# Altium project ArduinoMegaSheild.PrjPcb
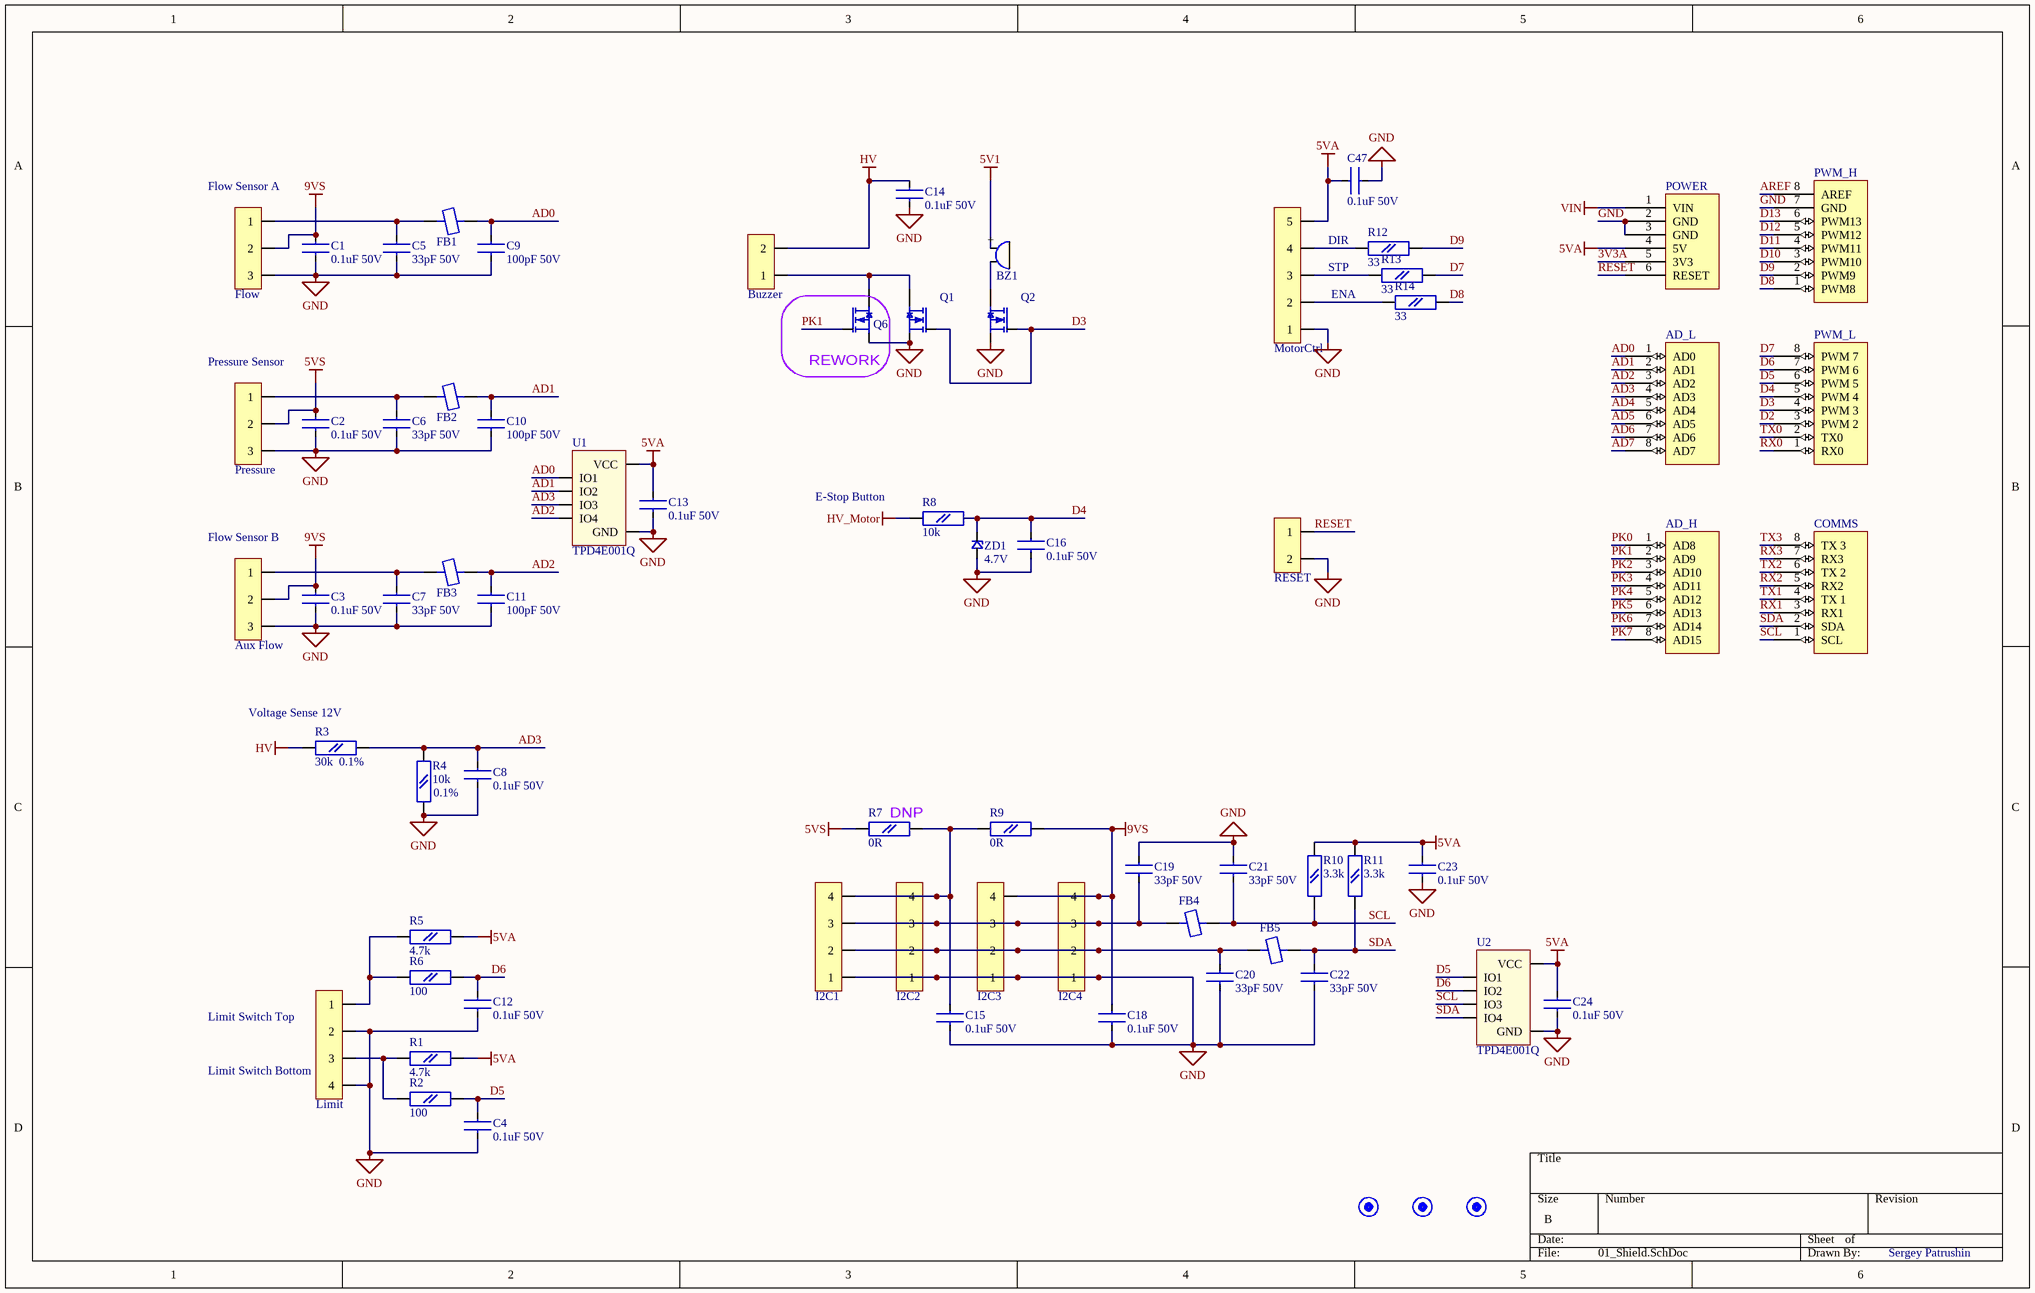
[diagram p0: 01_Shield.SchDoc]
3 sheets, 127 parts. Net scope: global (net labels, ports and power ports of the same name join across sheets).
Board file: MEGA_Shield_OVVP.pcbdoc
Sheets:
  01_Shield.SchDoc
  02_Power.SchDoc
  03_RPi.SchDoc

## Sheet 01_Shield.SchDoc
size B

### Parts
AD_H  AD_H  [Header 8x1 8.5mm]  (value not drawn)
AD_L  AD_L  [Header 8x1 8.5mm]  (value not drawn)
Aux_Flow  3pin JST  [3pin JST XH 2.5mm]  (value not drawn)
Buzzer  2pin JST  [2pin JST XH 2.5mm]  (value not drawn)
BZ1  BUZZER, 12mm X 9.5mm  [Buzzer]  (value not drawn)
C1  0.1uF 50V  [C np SMD 0805]
C2  0.1uF 50V  [C np SMD 0805]
C3  0.1uF 50V  [C np SMD 0805]
C4  0.1uF 50V  [C np SMD 0805]
C5  33pF 50V  [C np SMD 0805]
C6  33pF 50V  [C np SMD 0805]
C7  33pF 50V  [C np SMD 0805]
C8  0.1uF 50V  [C np SMD 0805]
C9  100pF 50V  [C np SMD 0805]
C10  100pF 50V  [C np SMD 0805]
C11  100pF 50V  [C np SMD 0805]
C12  0.1uF 50V  [C np SMD 0805]
C13  0.1uF 50V  [C np SMD 0805]
C14  0.1uF 50V  [C np SMD 0805]
C15  0.1uF 50V  [C np SMD 0805]
C16  0.1uF 50V  [C np SMD 0805]
C18  0.1uF 50V  [C np SMD 0805]
C19  33pF 50V  [C np SMD 0805]
C20  33pF 50V  [C np SMD 0805]
C21  33pF 50V  [C np SMD 0805]
C22  33pF 50V  [C np SMD 0805]
C23  0.1uF 50V  [C np SMD 0805]
C24  0.1uF 50V  [C np SMD 0805]
C47  0.1uF 50V  [C np SMD 0805]
COMMS  Communication  [Header 8x1 8.5mm]  (value not drawn)
F1  FIDUCIAL  [FIDUCIAL]  (value not drawn)
F2  FIDUCIAL  [FIDUCIAL]  (value not drawn)
F3  FIDUCIAL  [FIDUCIAL]  (value not drawn)
FB1  400mA  [R SMD 0805]  (value not drawn)
FB2  400mA  [R SMD 0805]  (value not drawn)
FB3  400mA  [R SMD 0805]  (value not drawn)
FB4  400mA  [R SMD 0805]  (value not drawn)
FB5  400mA  [R SMD 0805]  (value not drawn)
Flow  3pin JST  [3pin JST XH 2.5mm]  (value not drawn)
I2C1  4pin JST  [4pin JST XH 2.5mm]  (value not drawn)
I2C2  4pin JST  [4pin JST XH 2.5mm]  (value not drawn)
I2C3  4pin JST  [4pin JST XH 2.5mm]  (value not drawn)
I2C4  4pin JST  [4pin JST XH 2.5mm]  (value not drawn)
Limit  4pin JST  [4pin JST XH 2.5mm]  (value not drawn)
MotorCtrl  5pin JST  [5pin JST XH 2.5mm]  (value not drawn)
POWER  POWER  [Header 6x1 8.5mm]  (value not drawn)
Pressure  3pin JST  [3pin JST XH 2.5mm]  (value not drawn)
PWM_H  PWM_H  [Header 8x1 8.5mm]  (value not drawn)
PWM_L  PWM_L  [Header 8x1 8.5mm]  (value not drawn)
Q1  SOT23  [SOT23]  (value not drawn)
Q2  SOT23  [SOT23]  (value not drawn)
Q6  SOT23  [SOT23]  (value not drawn)
R1  4.7k  [R SMD 0805]
R2  100  [R SMD 0805]
R3  30k  [R SMD 0805]
R4  10k  [R SMD 0805]
R5  4.7k  [R SMD 0805]
R6  100  [R SMD 0805]
R7  0R  [R SMD 0805]
R8  10k  [R SMD 0805]
R9  0R  [R SMD 0805]
R10  3.3k  [R SMD 0805]
R11  3.3k  [R SMD 0805]
R12  33  [R SMD 0805]
R13  33  [R SMD 0805]
R14  33  [R SMD 0805]
RESET  1ROW HEADER 2PIN  [1ROW HEADER 2PIN]  (value not drawn)
U1  TPD4E001Q  [SOT-23-6]
U2  TPD4E001Q  [SOT-23-6]
ZD1  4.7V  [LL34]

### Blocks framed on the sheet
REWORK: Q6

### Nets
5V1: BZ1.+
5VA: C13.2 C23.1 C24.2 C47.1 MotorCtrl.5 POWER.4(5V) R1.2 R5.2 R10.2 R11.2 U1.5(VCC) U2.5(VCC)
5VS: C2.2 Pressure.2 R7.1
9VS: Aux_Flow.2 C1.2 C3.2 C18.2 Flow.2 I2C3.4 I2C4.4 R9.2
GND: Aux_Flow.3 C1.1 C2.1 C3.1 C4.1 C5.1 C6.1 C7.1 C8.1 C9.1 C10.1 C11.1 C12.1 C13.1 C14.1 C15.1 C16.1 C18.1 C19.2 C20.1 C21.2 C22.1 C23.2 C24.1 C47.2 Flow.3 I2C1.1 I2C2.1 I2C3.1 I2C4.1 Limit.2 Limit.4 MotorCtrl.1 POWER.2(GND) POWER.3(GND) Pressure.3 PWM_H.7(GND) Q1.S Q2.S Q6.S R4.2 RESET.2 U1.2(GND) U2.2(GND) ZD1.A
HV: Buzzer.2 C14.2 R3.1
HV_Motor: R8.2
VIN: POWER.1(VIN)
3V3A: POWER.5(3V3)
AD0: AD_L.1(AD0) C9.2 FB1.1 U1.1(IO1)
AD1: AD_L.2(AD1) C10.2 FB2.1 U1.3(IO2)
AD2: AD_L.3(AD2) C11.2 FB3.1 U1.6(IO4)
AD3: AD_L.4(AD3) C8.2 R3.2 R4.1 U1.4(IO3)
AD4: AD_L.5(AD4)
AD5: AD_L.6(AD5)
AD6: AD_L.7(AD6)
AD7: AD_L.8(AD7)
AREF: PWM_H.8(AREF)
D2: PWM_L.3(PWM_2)
D3: PWM_L.4(PWM_3) Q1.G Q2.G
D4: C16.2 PWM_L.5(PWM_4) R8.1 ZD1.K
D5: C4.2 PWM_L.6(PWM_5) R2.2 U2.1(IO1)
D6: C12.2 PWM_L.7(PWM_6) R6.2 U2.3(IO2)
D7: PWM_L.8(PWM_7) R13.2
D8: PWM_H.1(PWM8) R14.2
D9: PWM_H.2(PWM9) R12.2
D10: PWM_H.3(PWM10)
D11: PWM_H.4(PWM11)
D12: PWM_H.5(PWM12)
D13: PWM_H.6(PWM13)
PK0: AD_H.1(AD8)
PK1: AD_H.2(AD9) Q6.G
PK2: AD_H.3(AD10)
PK3: AD_H.4(AD11)
PK4: AD_H.5(AD12)
PK5: AD_H.6(AD13)
PK6: AD_H.7(AD14)
PK7: AD_H.8(AD15)
RESET: POWER.6(RESET) RESET.1
RX0: PWM_L.1(RX0)
RX1: COMMS.3(RX1)
RX2: COMMS.5(RX2)
RX3: COMMS.7(RX3)
SCL: C21.1 COMMS.1(SCL) FB4.2 R10.1 U2.4(IO3)
SDA: C22.2 COMMS.2(SDA) FB5.2 R11.1 U2.6(IO4)
TX0: PWM_L.2(TX0)
TX1: COMMS.4(TX_1)
TX2: COMMS.6(TX_2)
TX3: COMMS.8(TX_3)
NetAux_Flow_1: Aux_Flow.1 C7.2 FB3.2
NetBuzzer_1: Buzzer.1 Q1.D Q6.D
NetBZ1_-: BZ1.- Q2.D
NetC5_2: C5.2 FB1.2 Flow.1
NetC6_2: C6.2 FB2.2 Pressure.1
NetC15_2: C15.2 I2C1.4 I2C2.4 R7.2 R9.1
NetC19_1: C19.1 FB4.1 I2C1.3 I2C2.3 I2C3.3 I2C4.3
NetC20_2: C20.2 FB5.1 I2C1.2 I2C2.2 I2C3.2 I2C4.2
NetLimit_1: Limit.1 R5.1 R6.1
NetLimit_3: Limit.3 R1.1 R2.1
NetMotorCtrl_2: MotorCtrl.2 R14.1
NetMotorCtrl_3: MotorCtrl.3 R13.1
NetMotorCtrl_4: MotorCtrl.4 R12.1

Not connected (* = marked no-connect by the designer): F1 0; F2 0; F3 0

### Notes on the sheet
- (near Flow) Flow Sensor A
- (near MotorCtrl) DIR
- (near MotorCtrl) STP
- (near MotorCtrl) ENA
- (near Pressure) Pressure Sensor
- (near R8) E-Stop Button
- (near Aux_Flow) Flow Sensor B
- (near R3) Voltage Sense 12V
- (near R3) 0.1%
- (near R4) 0.1%
- (near R7) DNP
- (near Limit) Limit Switch Top
- (near Limit) Limit Switch Bottom
- Sergey Patrushin

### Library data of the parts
BZ1 = Buzzer 5V
C1-C4 C8 C12-C16 C18 C23 C24 C47 = C 0.1uF 50V SMD 0805
C5-C7 C19-C22 = C 33pF 50V SMD 0805
C9-C11 = C 100pF 50V SMD 0805
FB1-FB5 = Ferrite bead SMD 0805: 400mA, 0.2ohm, 220ohm @100MHz
Q1 Q2 Q6 = MOSFET N-ch SOT23: pin to pad: D>3 G>1 S>2
R1 R5 = R 4k7 1/8W SMD 0805
R2 R6 = R 100 1/8W SMD 0805
R3 = R 30k 1/8W SMD 0805
R4 R8 = R 10k 1/8W SMD 0805
R7 R9 = R 0R 1/8W SMD 0805
R10 R11 = R 3k3 1/8W SMD 0805
R12-R14 = R 33 1/8W SMD 0805
ZD1 = Zener 4.7V

## Sheet 02_Power.SchDoc
size B
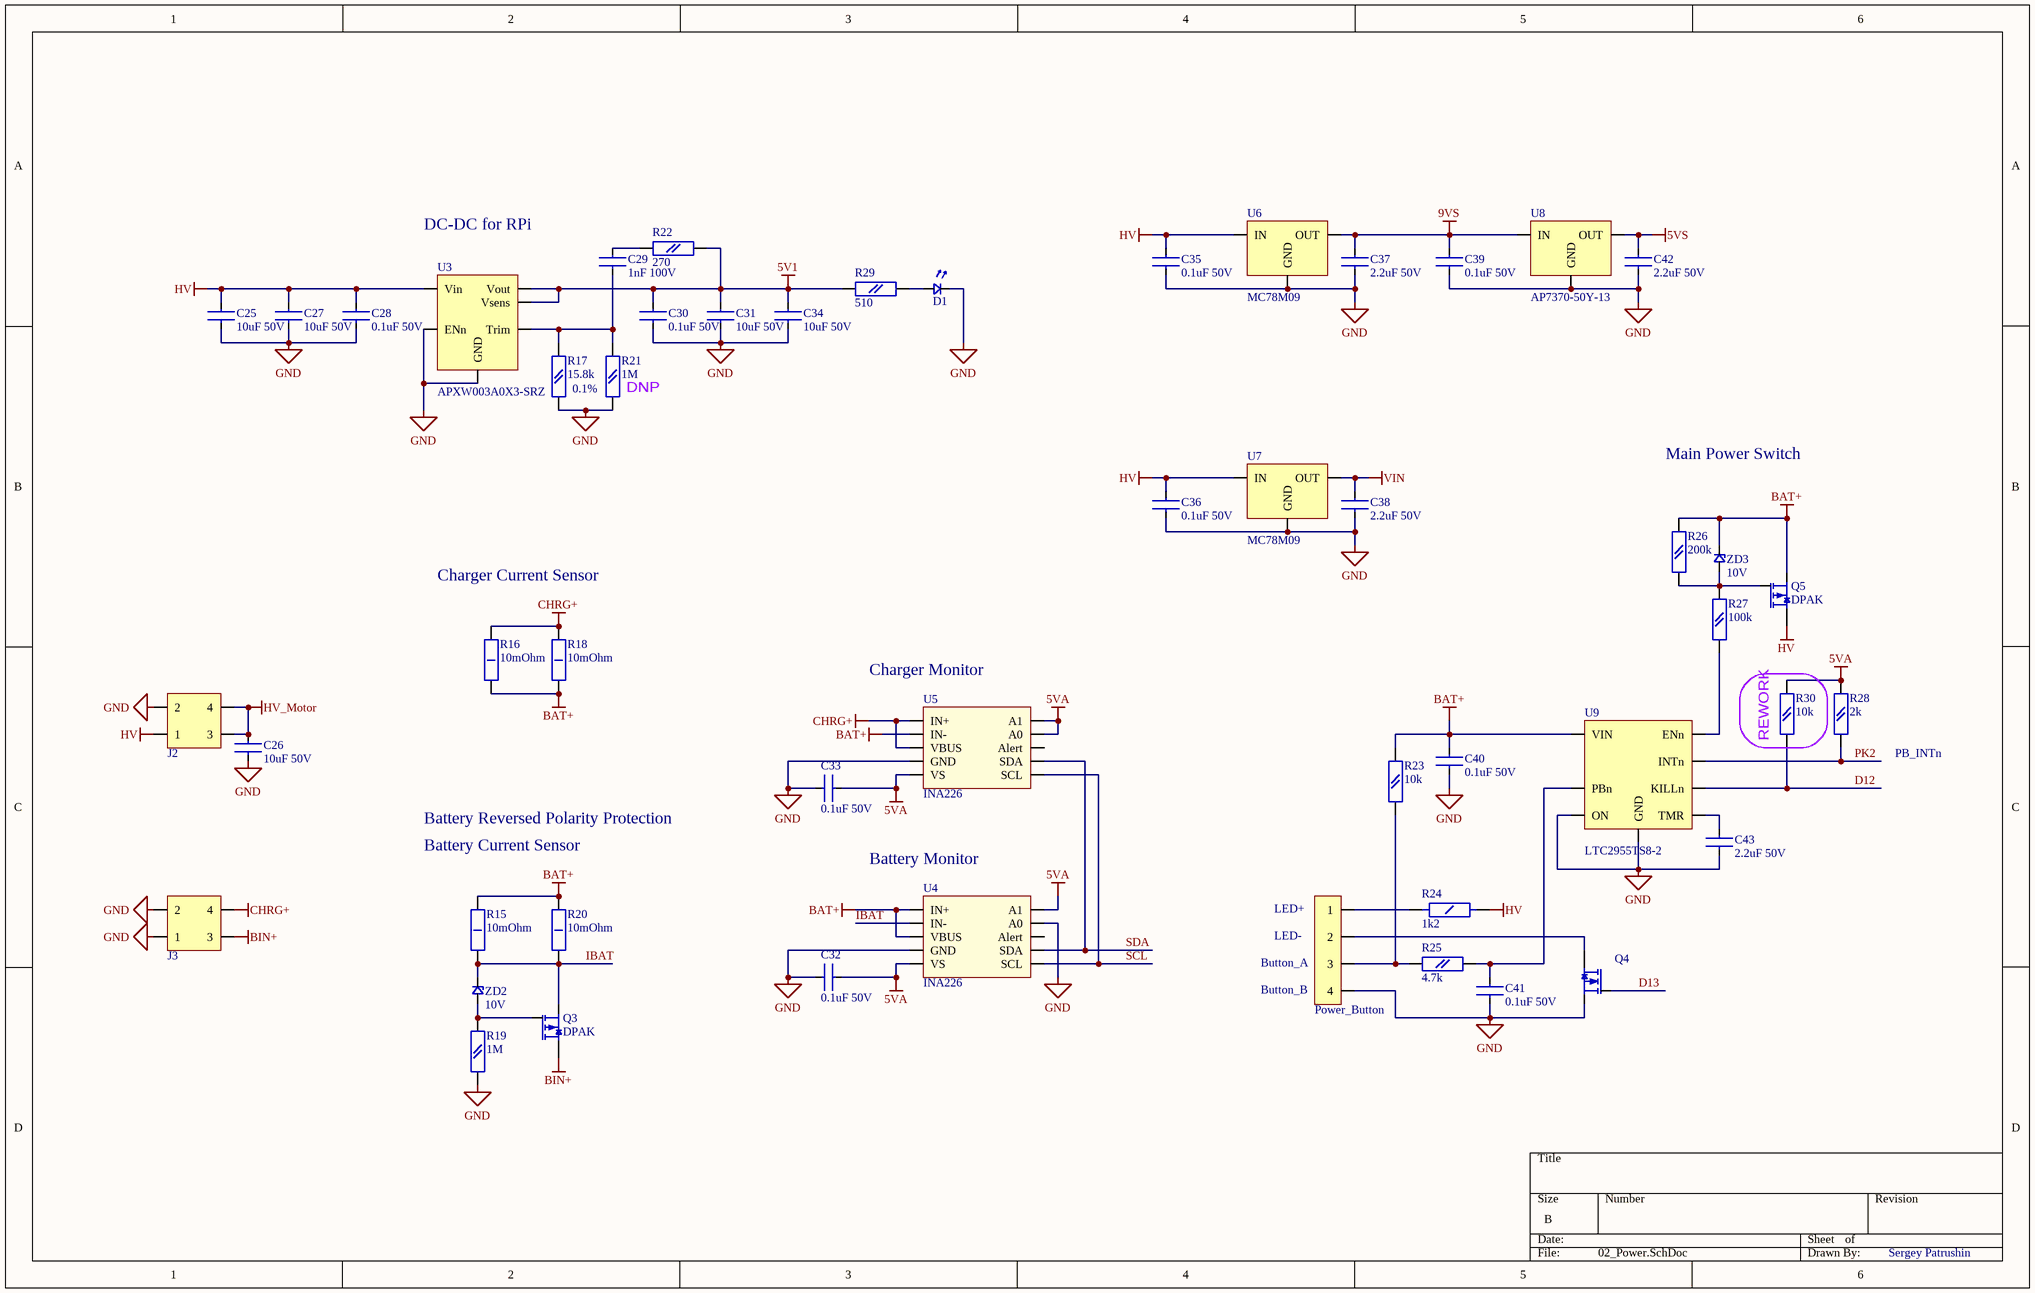
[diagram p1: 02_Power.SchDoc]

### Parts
C25  10uF 50V  [C np SMD 1206]
C26  10uF 50V  [C np SMD 1206]
C27  10uF 50V  [C np SMD 1206]
C28  0.1uF 50V  [C np SMD 0805]
C29  1nF 100V  [C np SMD 0805]
C30  0.1uF 50V  [C np SMD 0805]
C31  10uF 50V  [C np SMD 1206]
C32  0.1uF 50V  [C np SMD 0805]
C33  0.1uF 50V  [C np SMD 0805]
C34  10uF 50V  [C np SMD 1206]
C35  0.1uF 50V  [C np SMD 0805]
C36  0.1uF 50V  [C np SMD 0805]
C37  2.2uF 50V  [C np SMD 0805]
C38  2.2uF 50V  [C np SMD 0805]
C39  0.1uF 50V  [C np SMD 0805]
C40  0.1uF 50V  [C np SMD 0805]
C41  0.1uF 50V  [C np SMD 0805]
C42  2.2uF 50V  [C np SMD 0805]
C43  2.2uF 50V  [C np SMD 0805]
D1  LED SMD 0805  [LED SMD 0805]  (value not drawn)
J2  4pin JST VL  [4pin JST VL]  (value not drawn)
J3  4pin JST VL  [4pin JST VL]  (value not drawn)
Power_Button  4pin JST  [4pin JST XH 2.5mm]  (value not drawn)
Q3  DPAK  [DPAK]
Q4  SOT23  [SOT23]  (value not drawn)
Q5  DPAK  [DPAK]
R15  10mOhm  [R SMD 1206]
R16  10mOhm  [R SMD 1206]
R17  15.8k  [R SMD 0805]
R18  10mOhm  [R SMD 1206]
R19  1M  [R SMD 0805]
R20  10mOhm  [R SMD 1206]
R21  1M  [R SMD 0805]
R22  270  [R SMD 0805]
R23  10k  [R SMD 0805]
R24  1k2  [R L10 D2.5 W6.3]
R25  4.7k  [R SMD 0805]
R26  200k  [R SMD 0805]
R27  100k  [R SMD 0805]
R28  2k  [R SMD 0805]
R29  510  [R SMD 0805]
R30  10k  [R SMD 0805]
U3  APXW003A0X3-SRZ  [DC-DC ProLynx]
U4  INA226  [VSSOP10-TI]
U5  INA226  [VSSOP10-TI]
U6  MC78M09  [TO-252-3]
U7  MC78M09  [TO-252-3]
U8  AP7370-50Y-13  [SOT-89]
U9  LTC2955TS8-2  [TSOT-23-8-LTC]
ZD2  10V  [LL34]
ZD3  10V  [LL34]

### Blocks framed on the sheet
REWORK: R30

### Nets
5V1: C30.2 C31.2 C34.2 R22.2 R29.1 U3.Vout U3.Vsens
5VA: C32.1 C33.1 R28.2 R30.2 U4.1(A1) U4.6(VS) U5.1(A1) U5.2(A0) U5.6(VS)
5VS: C42.2 U8.OUT
9VS: C37.2 C39.2 U6.OUT U8.IN
BAT+: C40.2 Q5.S R15.2 R16.1 R18.1 R20.2 R23.2 R26.2 U4.8(VBUS) U4.10(IN+) U5.9(IN-) U9.6(VIN) ZD3.K
BIN+: J3.3 Q3.D
CHRG+: J3.4 R16.2 R18.2 U5.8(VBUS) U5.10(IN+)
GND: C25.1 C26.2 C27.1 C28.1 C30.1 C31.1 C32.2 C33.2 C34.1 C35.1 C36.1 C37.1 C38.1 C39.1 C40.1 C41.1 C42.1 C43.1 D1.C J2.2 J3.1 J3.2 Power_Button.4 Q4.S R17.1 R19.1 R21.1 U3.ENn U3.GND U4.2(A0) U4.7(GND) U5.7(GND) U6.GND U7.GND U8.GND U9.1(ON) U9.4(GND)
HV: C25.2 C27.2 C28.2 C35.2 C36.2 J2.1 Q5.D R24.2 U3.Vin U6.IN U7.IN
HV_Motor: C26.1 J2.3 J2.4
VIN: C38.2 U7.OUT
D12: R30.1 U9.2(KILLn)
D13: Q4.G
IBAT: Q3.S R15.1 R20.1 U4.9(IN-) ZD2.K
PK2: R28.1 U9.8(INTn)
SCL: U4.5(SCL) U5.5(SCL)
SDA: U4.4(SDA) U5.4(SDA)
NetC29_1: C29.1 R17.2 R21.2 U3.Trim
NetC29_2: C29.2 R22.1
NetC41_2: C41.2 R25.2 U9.5(PBn)
NetC43_2: C43.2 U9.3(TMR)
NetD1_A: D1.A R29.2
NetPower_Button_1: Power_Button.1 R24.1
NetPower_Button_2: Power_Button.2 Q4.D
NetPower_Button_3: Power_Button.3 R23.1 R25.1
NetQ3_G: Q3.G R19.2 ZD2.A
NetQ5_G: Q5.G R26.1 R27.2 ZD3.A
NetR27_1: R27.1 U9.7(ENn)

Not connected (* = marked no-connect by the designer): U4 3(Alert); U5 3(Alert)

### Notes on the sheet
- DC-DC for RPi
- 0.1%
- (near R21) DNP
- Main Power Switch
- Charger Current Sensor
- (near U5) Charger Monitor
- PB_INTn
- Battery Reversed Polarity Protection
- Battery Current Sensor
- (near U4) Battery Monitor
- (near Power_Button) LED+
- (near Power_Button) Button_A
- (near Power_Button) LED-
- (near Power_Button) Button_B
- Sergey Patrushin

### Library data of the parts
C25-C27 C31 C34 = C 10uF 50V SMD 1206
C28 C30 C32 C33 C35 C36 C39-C41 = C 0.1uF 50V SMD 0805
C29 = C 1nF 100V SMD 0805
C37 C38 C42 C43 = C 2.2uF 50V SMD 0805
Q3 Q5 = MOSFET P-ch DPAK: pin to pad: D>2 G>1 S>3
Q4 = MOSFET N-ch SOT23: pin to pad: D>3 G>1 S>2
R15 R16 R18 R20 = R 0.01R 1W SMD1206
R17 = R 15k8 1/8W SMD 0805
R19 R21 = R 1M 1/8W SMD 0805
R22 = R 270 1/8W SMD 0805
R23 R30 = R 10k 1/8W SMD 0805
R24 = R 1k2 1/4W
R25 = R 4k7 1/8W SMD 0805
R26 = R 200k 1/8W SMD 0805
R27 = R 100k 1/8W SMD 0805
R28 = R 2k 1/8W SMD 0805
R29 = R 510 1/8W SMD 0805
U6 U7 = LDO 9V TO-252: pin to pad: GND>2 IN>1 OUT>3
U8 = LDO 5V SOT-89: pin to pad: GND>2 IN>3 OUT>1
U9 = LTC2955-2
ZD2 ZD3 = Zener 10V

## Sheet 03_RPi.SchDoc
size B
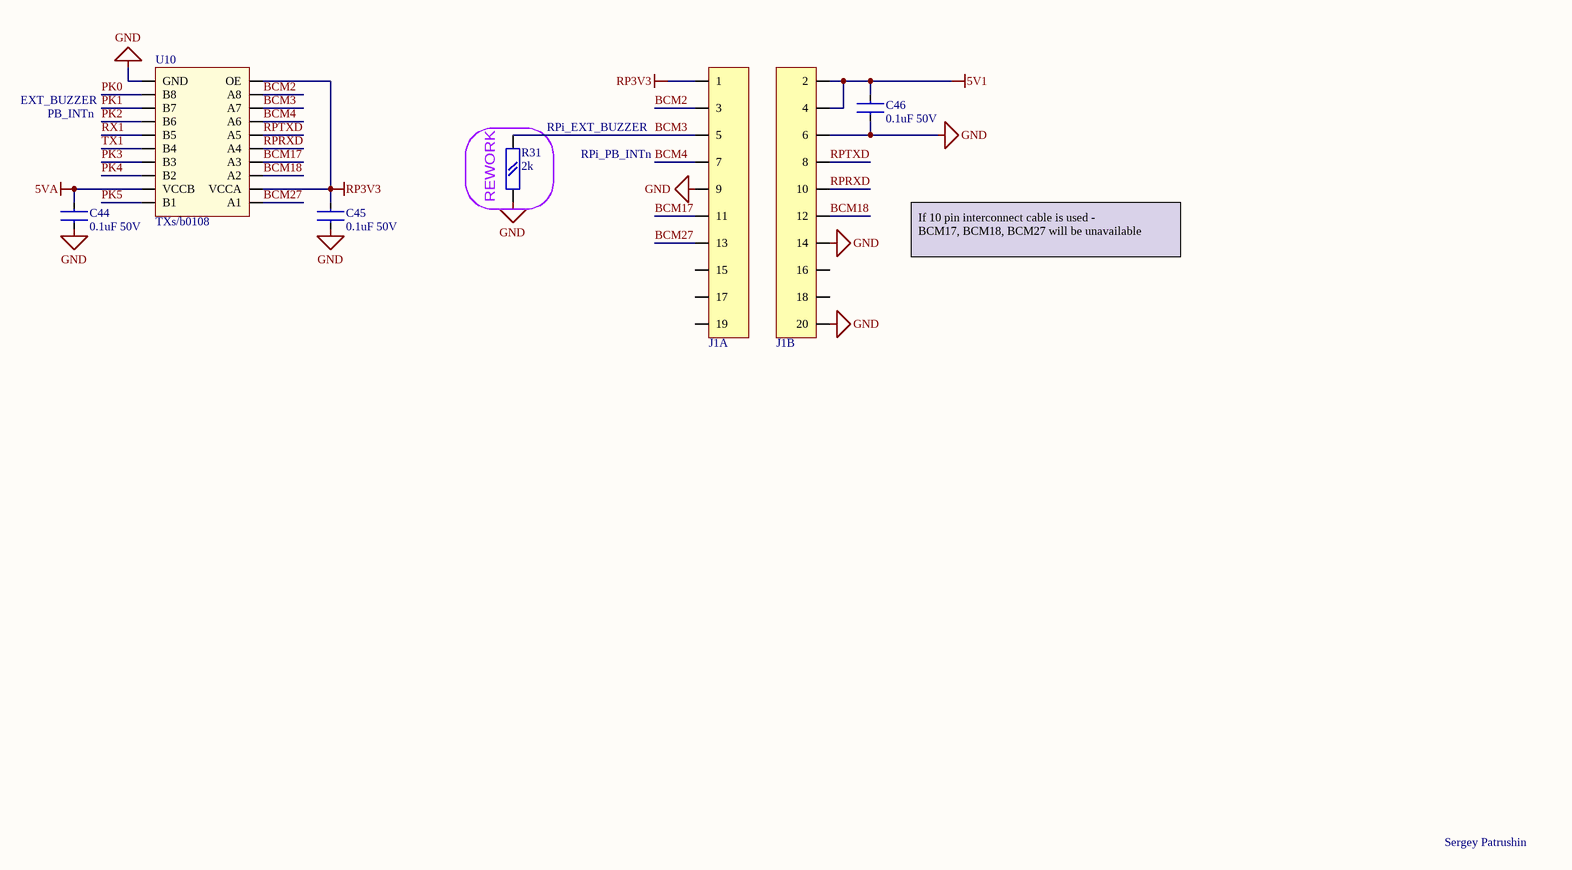
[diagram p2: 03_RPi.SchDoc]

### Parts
C44  0.1uF 50V  [C np SMD 0805]
C45  0.1uF 50V  [C np SMD 0805]
C46  0.1uF 50V  [C np SMD 0805]
J1  2ROW HEADER 20PIN  [2ROW HEADER 20PIN]  (value not drawn)  (parts A,B of 2)
R31  2k  [R SMD 0805]
U10  TXs/b0108  [TSSOP20-TI]

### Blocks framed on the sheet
REWORK: R31

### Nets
5V1: C46.2 J1.2 J1.4
5VA: C44.2 U10.19(VCCB)
GND: C44.1 C45.1 C46.1 J1.6 J1.9 J1.14 J1.20 R31.1 U10.11(GND)
RP3V3: C45.2 J1.1 U10.2(VCCA) U10.10(OE)
BCM2: J1.3 U10.9(A8)
BCM3: J1.5 R31.2 U10.8(A7)
BCM4: J1.7 U10.7(A6)
BCM17: J1.11 U10.4(A3)
BCM18: J1.12 U10.3(A2)
BCM27: J1.13 U10.1(A1)
PK0: U10.12(B8)
PK1: U10.13(B7)
PK2: U10.14(B6)
PK3: U10.17(B3)
PK4: U10.18(B2)
PK5: U10.20(B1)
RPRXD: J1.10 U10.5(A4)
RPTXD: J1.8 U10.6(A5)
RX1: U10.15(B5)
TX1: U10.16(B4)

Not connected (* = marked no-connect by the designer): J1 15 16 17 18 19

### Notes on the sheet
- EXT_BUZZER
- PB_INTn
- (near R31) RPi_EXT_BUZZER
- RPi_PB_INTn
- If 10 pin interconnect cable is used -
  BCM17, BCM18, BCM27 will be unavailable
- Sergey Patrushin

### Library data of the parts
C44-C46 = C 0.1uF 50V SMD 0805
R31 = R 2k 1/8W SMD 0805
U10 = TX_0108

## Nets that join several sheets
5V1: 01_Shield (BZ1.+), 02_Power (7 pins), 03_RPi (C46.2 J1.2 J1.4)
5VA: 01_Shield (12 pins), 02_Power (9 pins), 03_RPi (C44.2 U10.19)
5VS: 01_Shield (C2.2 Pressure.2 R7.1), 02_Power (C42.2 U8.OUT)
9VS: 01_Shield (8 pins), 02_Power (C37.2 C39.2 U6.OUT U8.IN)
GND: 01_Shield (45 pins), 02_Power (37 pins), 03_RPi (9 pins)
HV: 01_Shield (Buzzer.2 C14.2 R3.1), 02_Power (11 pins)
HV_Motor: 01_Shield (R8.2), 02_Power (C26.1 J2.3 J2.4)
VIN: 01_Shield (POWER.1), 02_Power (C38.2 U7.OUT)
D12: 01_Shield (PWM_H.5), 02_Power (R30.1 U9.2)
D13: 01_Shield (PWM_H.6), 02_Power (Q4.G)
PK0: 01_Shield (AD_H.1), 03_RPi (U10.12)
PK1: 01_Shield (AD_H.2 Q6.G), 03_RPi (U10.13)
PK2: 01_Shield (AD_H.3), 02_Power (R28.1 U9.8), 03_RPi (U10.14)
PK3: 01_Shield (AD_H.4), 03_RPi (U10.17)
PK4: 01_Shield (AD_H.5), 03_RPi (U10.18)
PK5: 01_Shield (AD_H.6), 03_RPi (U10.20)
RX1: 01_Shield (COMMS.3), 03_RPi (U10.15)
SCL: 01_Shield (5 pins), 02_Power (U4.5 U5.5)
SDA: 01_Shield (5 pins), 02_Power (U4.4 U5.4)
TX1: 01_Shield (COMMS.4), 03_RPi (U10.16)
